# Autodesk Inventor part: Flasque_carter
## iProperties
Shininess: 64.0
Length Units: 11269
Angle Units: 11279
Time Units: 11290
Mass Units: 11283
Length Display Precision: 3
Angle Display Precision: 2
Compacted: True
Part Number: Flasque_carter
Document SubType Name: Modeling
Created: 2008-02
Material: Acier inoxydable - 440C
Designer: Pascal
Density: 7.75 g/cm^3
Density: 0.0
Volumn: 0.0
Area: 0.0
PropertySet Name: Model Information
Control State: 0
Master: False
Checked Out: False
DESIGNATION: Flasque carter
Author: Pascal
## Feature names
1. Extrusion1
